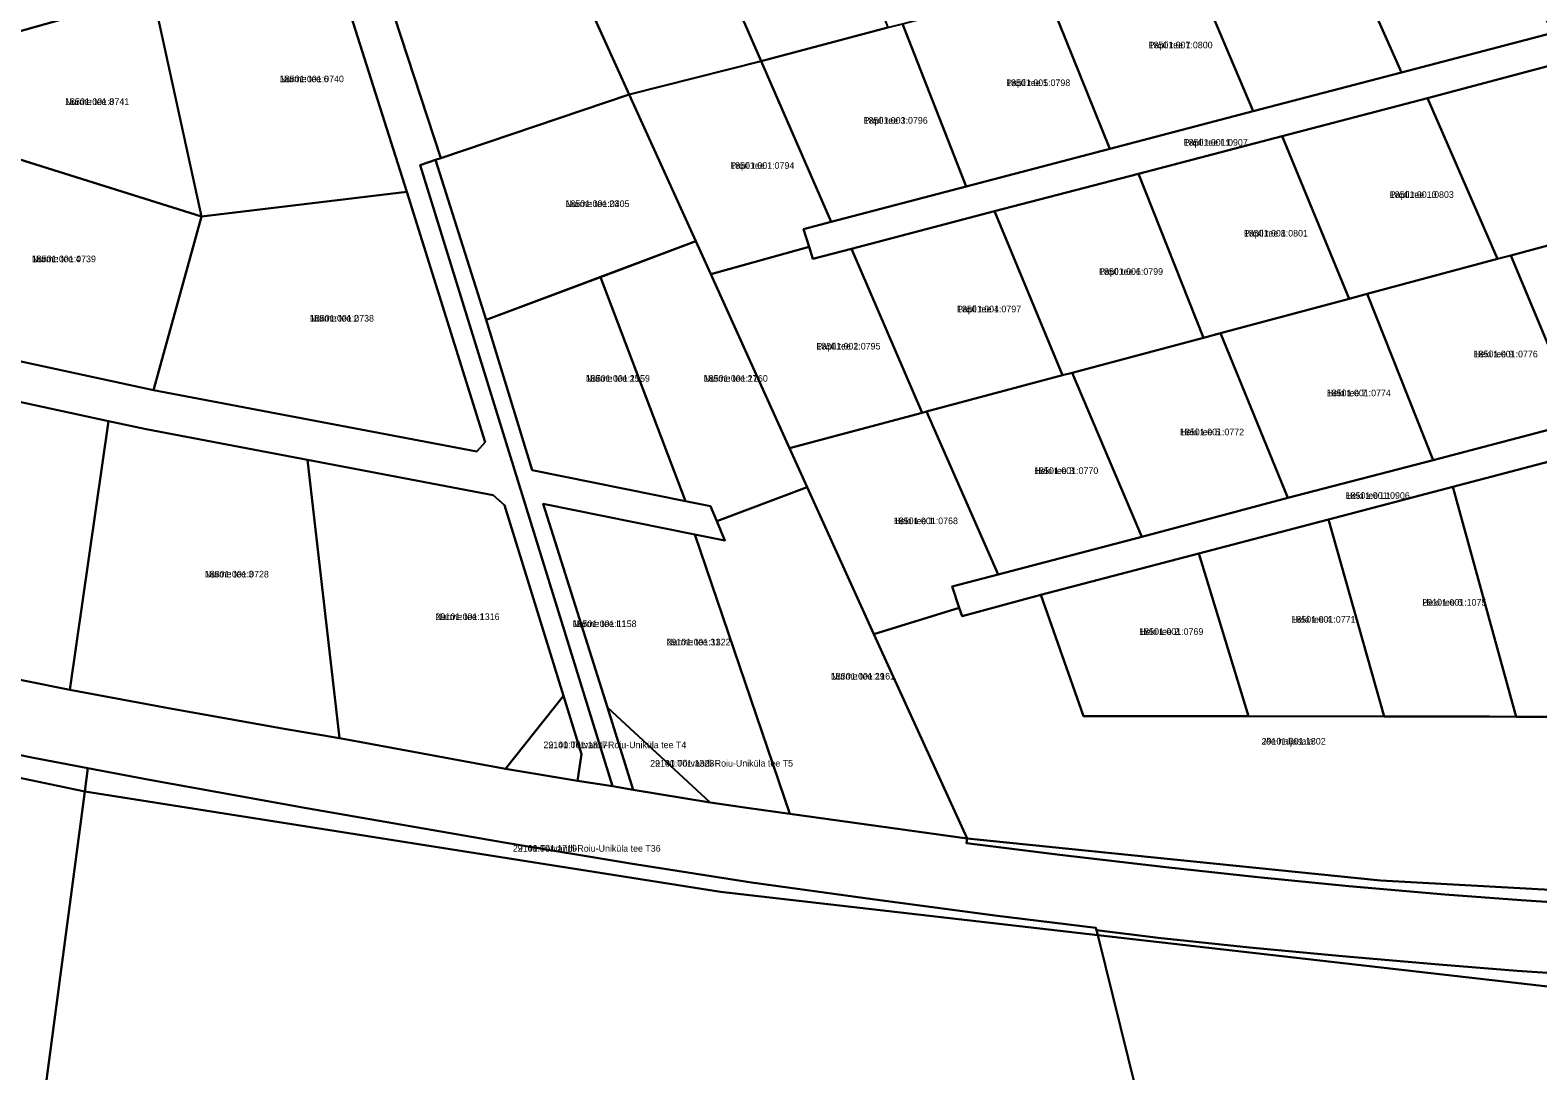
# Model space of a CAD drawing. Extents: x 660838 to 697091, y 6455678 to 6479886.
# Drawn here: x 663753.8 to 664095.1, y 6468179.9 to 6468415.5 of the extents above; entities that cross this region are included whole.
import ezdxf

# ---------------------------------------------------------------- set-up
doc = ezdxf.new("R2010")
doc.units = 0
for name, color, linetype in [('L_AADRESS', 7, 'Continuous'), ('PIIR', 7, 'Continuous'), ('TUNNUS', 7, 'Continuous')]:
    doc.layers.add(name, color=color, linetype=linetype)

msp = doc.modelspace()

# ---------------------------------------------------------------- linework, layer by layer
at = {"layer": 'PIIR'}
for points in [[(663828.73, 6468441.62), (663865.64, 6468453.42), (663871.74, 6468439.96), (663889.41, 6468400.95), (663846.76, 6468386.49)], [(663903.11, 6468445.49), (663933.58, 6468453.47), (663947.98, 6468416.06), (663919.26, 6468408.5)], [(664047.87, 6468442.82), (664071.93, 6468449.23), (664074.89, 6468442.69), (664082.82, 6468445.33), (664098.51, 6468414.91), (664064.26, 6468405.93)], [(663885.65, 6468244.29), (663877.74, 6468245.51), (663878.61, 6468251.58), (663874.54, 6468264.74), (663861.17, 6468307.93), (663858.61, 6468310.23), (663816.6, 6468318.2), (663780.04, 6468325.13), (663771.57, 6468326.94), (663725.97, 6468336.81), (663698.3, 6468342.78), (663700.87, 6468347.01), (663721.55, 6468388.74), (663737.12, 6468420.02), (663744.03, 6468422.46), (663780.76, 6468432.84), (663823.76, 6468445.04), (663828.73, 6468441.62), (663846.76, 6468386.49), (663845.6, 6468386.09), (663842.06, 6468384.89)], [(663871.75, 6468439.96), (663893.39, 6468446.27), (663894.39, 6468443.22), (663903.11, 6468445.49), (663919.26, 6468408.5), (663889.41, 6468400.95)], [(664015.04, 6468434.01), (664042.8, 6468441.46), (664047.87, 6468442.82), (664064.26, 6468405.93), (664030.62, 6468397.11)], [(663854.89, 6468320.1), (663856.77, 6468322.23), (663839.06, 6468378.91), (663821.86, 6468433.12), (663819.34, 6468434.52), (663781.58, 6468423.81), (663747.74, 6468414.2), (663742.48, 6468410.94), (663733.1, 6468391.92), (663713.01, 6468351.64), (663714.75, 6468348.46), (663781.7, 6468333.97)], [(663781.58, 6468423.81), (663819.34, 6468434.52), (663821.86, 6468433.12), (663839.06, 6468378.91), (663792.61, 6468373.3)], [(663983.33, 6468425.52), (664010.69, 6468432.82), (664015.04, 6468434.01), (664030.62, 6468397.11), (663998.2, 6468388.6)], [(663733.1, 6468391.92), (663742.48, 6468410.94), (663747.74, 6468414.2), (663781.58, 6468423.81), (663792.61, 6468373.3)], [(663951.27, 6468416.94), (663978.87, 6468424.33), (663983.33, 6468425.52), (663998.2, 6468388.6), (663965.71, 6468380.05)], [(663919.26, 6468408.5), (663947.98, 6468416.06), (663951.27, 6468416.94), (663965.71, 6468380.05), (663935.15, 6468372.06)], [(664098.51, 6468414.91), (664101.86, 6468408.55), (664070.12, 6468400.11), (664037.18, 6468391.48), (664004.69, 6468382.98), (663972.11, 6468374.47), (663939.71, 6468366), (663931.01, 6468363.73), (663930.12, 6468366.43), (663928.84, 6468370.43), (663935.15, 6468372.06), (663965.71, 6468380.05), (663998.2, 6468388.6), (664030.62, 6468397.11), (664064.26, 6468405.93)], [(663889.41, 6468400.95), (663919.26, 6468408.5), (663935.15, 6468372.06), (663928.84, 6468370.43), (663930.12, 6468366.43), (663907.86, 6468360.21), (663904.5, 6468367.7)], [(664070.12, 6468400.11), (664101.86, 6468408.55), (664119.99, 6468372.84), (664088.98, 6468364.5), (664085.96, 6468363.69)], [(663845.6, 6468386.09), (663846.76, 6468386.49), (663889.41, 6468400.95), (663904.5, 6468367.7), (663857.02, 6468349.93)], [(664037.18, 6468391.48), (664070.12, 6468400.11), (664085.96, 6468363.69), (664056.43, 6468355.76), (664052.4, 6468354.68)], [(663733.1, 6468391.92), (663792.61, 6468373.3), (663781.7, 6468333.97), (663714.75, 6468348.46), (663713.01, 6468351.64)], [(664004.69, 6468382.98), (664037.18, 6468391.48), (664052.4, 6468354.68), (664023.22, 6468346.87), (664019.39, 6468345.85)], [(663885.65, 6468244.29), (663842.06, 6468384.89), (663845.6, 6468386.09), (663857.02, 6468349.93), (663867.45, 6468315.88), (663902.18, 6468308.87), (663907.84, 6468307.73), (663909.27, 6468304.28), (663911.09, 6468299.93), (663904.24, 6468301.31), (663869.9, 6468308.24), (663884.46, 6468262.13), (663890.31, 6468243.48)], [(663972.11, 6468374.47), (664004.69, 6468382.98), (664019.39, 6468345.85), (663989.7, 6468337.93), (663987.53, 6468337.35)], [(663792.61, 6468373.3), (663839.06, 6468378.91), (663856.77, 6468322.23), (663854.89, 6468320.1), (663781.7, 6468333.97)], [(663939.71, 6468366), (663972.11, 6468374.47), (663987.53, 6468337.35), (663956.72, 6468329.11), (663955.71, 6468328.84)], [(664088.98, 6468364.5), (664119.99, 6468372.84), (664138.93, 6468335.94), (664104.7, 6468326.9)], [(663882.88, 6468359.55), (663904.5, 6468367.7), (663907.86, 6468360.21), (663925.72, 6468320.81), (663929.69, 6468312.03), (663909.27, 6468304.28), (663907.84, 6468307.73), (663902.18, 6468308.87)], [(663907.86, 6468360.21), (663930.12, 6468366.43), (663931.01, 6468363.73), (663939.71, 6468366), (663955.71, 6468328.84), (663925.72, 6468320.81)], [(664056.43, 6468355.76), (664085.96, 6468363.69), (664088.98, 6468364.5), (664104.7, 6468326.9), (664071.43, 6468318.15)], [(663857.02, 6468349.93), (663882.88, 6468359.55), (663902.18, 6468308.87), (663867.45, 6468315.88)], [(664023.22, 6468346.87), (664052.4, 6468354.68), (664056.43, 6468355.76), (664071.43, 6468318.15), (664038.5, 6468309.59)], [(663989.7, 6468337.93), (664019.39, 6468345.85), (664023.22, 6468346.87), (664038.5, 6468309.59), (664005.47, 6468300.79)], [(663956.72, 6468329.11), (663987.53, 6468337.35), (663989.7, 6468337.93), (664005.47, 6468300.79), (663972.93, 6468292.22)], [(663725.97, 6468336.81), (663771.57, 6468326.94), (663762.81, 6468266.1), (663731.63, 6468272.38), (663706.42, 6468277.94)], [(664138.93, 6468335.94), (664142.09, 6468329.5), (664103.67, 6468319.4), (664075.84, 6468312.07), (664047.71, 6468304.7), (664018.32, 6468296.96), (663982.59, 6468287.6), (663964.77, 6468282.8), (663964.11, 6468284.71), (663962.55, 6468289.49), (663972.93, 6468292.22), (664005.47, 6468300.79), (664038.5, 6468309.59), (664071.43, 6468318.15), (664104.7, 6468326.9)], [(663925.72, 6468320.81), (663955.71, 6468328.84), (663956.72, 6468329.11), (663972.93, 6468292.22), (663962.55, 6468289.49), (663964.11, 6468284.71), (663944.79, 6468278.74)], [(663771.57, 6468326.94), (663780.04, 6468325.13), (663816.6, 6468318.2), (663823.87, 6468255.19), (663811.79, 6468257.22), (663785.11, 6468262), (663762.81, 6468266.1)], [(663816.6, 6468318.2), (663858.61, 6468310.23), (663861.17, 6468307.93), (663874.54, 6468264.74), (663861.38, 6468248.23), (663823.87, 6468255.19)], [(664075.84, 6468312.07), (664103.67, 6468319.4), (664112.78, 6468291.23), (664111.41, 6468290.88), (664119.66, 6468259.88), (664105.73, 6468259.99), (664090.17, 6468260.05)], [(663909.27, 6468304.28), (663929.69, 6468312.03), (663944.79, 6468278.74), (663965.92, 6468232.47), (663925.77, 6468238.06), (663904.24, 6468301.31), (663911.09, 6468299.93)], [(664047.71, 6468304.7), (664075.84, 6468312.07), (664090.17, 6468260.05), (664084.21, 6468260.09), (664060.31, 6468260.11)], [(663916.01, 6468239.42), (663907.71, 6468240.63), (663884.46, 6468262.13), (663869.9, 6468308.24), (663904.24, 6468301.31), (663925.77, 6468238.06)], [(664018.32, 6468296.96), (664047.71, 6468304.7), (664060.31, 6468260.11), (664029.61, 6468260.17)], [(663982.59, 6468287.6), (664018.32, 6468296.96), (664029.61, 6468260.17), (663992.24, 6468260.2)], [(664117.34, 6468237.15), (664115.71, 6468219.88), (664059.46, 6468222.99), (663965.92, 6468232.47), (663944.79, 6468278.74), (663964.11, 6468284.71), (663964.77, 6468282.8), (663982.59, 6468287.6), (663992.24, 6468260.2), (664029.61, 6468260.17), (664060.31, 6468260.11), (664084.21, 6468260.09), (664090.17, 6468260.05), (664105.73, 6468259.99)], [(663861.38, 6468248.23), (663874.54, 6468264.74), (663878.61, 6468251.58), (663877.74, 6468245.51)], [(663890.31, 6468243.48), (663884.46, 6468262.13), (663907.71, 6468240.63)], [(663910.1, 6468220.42), (663766.16, 6468243.11), (663766.86, 6468248.39), (663780.85, 6468245.76), (663816.37, 6468239.37), (663861.1, 6468231.54), (663889.69, 6468226.78), (663917.07, 6468222.48), (663944.51, 6468218.73), (663972.18, 6468215.04), (663995.06, 6468212.27), (663995.18, 6468211.75), (663995.49, 6468210.56)], [(663965.79, 6468231.38), (663965.92, 6468232.47), (664059.46, 6468222.99), (664115.71, 6468219.88), (664117.34, 6468237.15), (664156.34, 6468234.74), (664171.5, 6468242.59), (664182.99, 6468248.64), (664186.43, 6468241.89), (664201.65, 6468212.63), (664200.48, 6468211.55), (664165.54, 6468213.74), (664122.2, 6468216.46), (664091.28, 6468218.5), (664074.07, 6468219.81), (664052.27, 6468221.67), (664031.71, 6468223.7), (664010.87, 6468226), (663986.88, 6468228.81)], [(663734.7, 6468006.73), (663766.16, 6468243.11), (663910.1, 6468220.42), (663995.49, 6468210.56), (664057.12, 6467961.27), (664125.46, 6467683.34), (663559.65, 6467851.27), (663625.35, 6468044.77), (663626.65, 6468048.6), (663734.39, 6468004.41)], [(664148.88, 6468193.07), (663995.49, 6468210.56), (663995.18, 6468211.75), (664009.18, 6468210.01), (664029.84, 6468207.79), (664050.89, 6468205.83), (664072.71, 6468203.97), (664090.44, 6468202.53), (664121.17, 6468200.49), (664154.73, 6468198.28), (664156.38, 6468189.18)], [(664057.12, 6467961.27), (663995.49, 6468210.56), (664148.88, 6468193.07), (664156.38, 6468189.18), (664156.84, 6468186.18), (664188.82, 6468093.34), (664212.9, 6468021.9), (664222.24, 6467993.73), (664224.85, 6467985.32)]]:
    msp.add_lwpolyline(points, close=True, dxfattribs=at)
for points in [[(663573.38, 6468283.55), (663766.16, 6468243.11), (663734.7, 6468006.73)], [(663727.84, 6468256.2), (663754.55, 6468250.71), (663766.86, 6468248.39), (663766.16, 6468243.11), (663573.38, 6468283.55)], [(663731.63, 6468272.38), (663762.81, 6468266.1), (663785.11, 6468262), (663811.79, 6468257.22), (663823.87, 6468255.19), (663861.38, 6468248.23), (663877.74, 6468245.51), (663885.65, 6468244.29), (663890.31, 6468243.48), (663907.71, 6468240.63), (663916.01, 6468239.42), (663925.77, 6468238.06), (663965.92, 6468232.47), (663965.79, 6468231.38), (663986.88, 6468228.81), (664010.87, 6468226), (664031.71, 6468223.7), (664052.27, 6468221.67), (664074.07, 6468219.81), (664091.28, 6468218.5), (664122.2, 6468216.46)], [(664121.17, 6468200.49), (664090.44, 6468202.53), (664072.71, 6468203.97), (664050.89, 6468205.83), (664029.84, 6468207.79), (664009.18, 6468210.01), (663995.18, 6468211.75), (663995.06, 6468212.27), (663972.18, 6468215.04), (663944.51, 6468218.73), (663917.07, 6468222.48), (663889.69, 6468226.78), (663861.1, 6468231.54), (663816.37, 6468239.37), (663780.85, 6468245.76), (663766.86, 6468248.39), (663754.55, 6468250.71), (663727.84, 6468256.2)]]:
    msp.add_lwpolyline(points, dxfattribs=at)

# ---------------------------------------------------------------- texts
at = {"layer": 'L_AADRESS'}
for s, p in [('Papli tee 7', (664006.97, 6468411.37)), ('Nurme tee 6', (663810.32, 6468403.7)), ('Papli tee 5', (663974.74, 6468402.82)), ('Nurme tee 8', (663761.73, 6468398.55)), ('Papli tee 3', (663942.48, 6468394.3)), ('Papli tee L1', (664014.93, 6468389.32)), ('Papli tee 1', (663912.28, 6468384.09)), ('Papli tee 10', (664061.57, 6468377.51)), ('Nurme tee 23', (663874.98, 6468375.44)), ('Papli tee 8', (664028.54, 6468368.76)), ('Nurme tee 4', (663754.19, 6468362.95)), ('Papli tee 6', (663995.75, 6468360.09)), ('Papli tee 4', (663963.62, 6468351.6)), ('Nurme tee 2', (663817.13, 6468349.51)), ('Papli tee 2', (663931.79, 6468343.18)), ('Heki tee 9', (664080.57, 6468341.4)), ('Nurme tee 25', (663879.6, 6468335.88)), ('Nurme tee 27', (663906.29, 6468335.88)), ('Heki tee 7', (664047.32, 6468332.6)), ('Heki tee 5', (664014.1, 6468323.76)), ('Heki tee 3', (663981.09, 6468315)), ('Heki tee L1', (664051.6, 6468309.37)), ('Heki tee 1', (663949.32, 6468303.64)), ('Nurme tee 3', (663793.34, 6468291.57)), ('Heki tee 6', (664068.94, 6468285.18)), ('Nurme tee 1', (663845.57, 6468281.93)), ('Nurme tee L1', (663876.58, 6468280.33)), ('Heki tee 2', (664004.87, 6468278.57)), ('Heki tee 4', (664039.32, 6468281.32)), ('Nurme tee 31', (663897.84, 6468276.18)), ('Nurme tee 29', (663935.08, 6468268.46)), ('22140 Tõrvandi-Roiu-Uniküla tee T4', (663870, 6468252.92)), ('Jõe haljasala', (664032.56, 6468253.74)), ('22140 Tõrvandi-Roiu-Uniküla tee T5', (663894.16, 6468248.75)), ('22140 Tõrvandi-Roiu-Uniküla tee T36', (663863.08, 6468229.48))]:
    msp.add_text(s, height=1.5, dxfattribs=at).set_placement(p)
at = {"layer": 'TUNNUS'}
for s, p in [('18501:001:0800', (664006.97, 6468411.37)), ('18501:001:0740', (663810.32, 6468403.7)), ('18501:001:0798', (663974.74, 6468402.82)), ('18501:001:0741', (663761.73, 6468398.55)), ('18501:001:0796', (663942.48, 6468394.3)), ('18501:001:0907', (664014.93, 6468389.32)), ('18501:001:0794', (663912.28, 6468384.09)), ('18501:001:0803', (664061.57, 6468377.51)), ('18501:001:0405', (663874.98, 6468375.44)), ('18501:001:0801', (664028.54, 6468368.76)), ('18501:001:0739', (663754.19, 6468362.95)), ('18501:001:0799', (663995.75, 6468360.09)), ('18501:001:0797', (663963.62, 6468351.6)), ('18501:001:0738', (663817.13, 6468349.51)), ('18501:001:0795', (663931.79, 6468343.18)), ('18501:001:0776', (664080.57, 6468341.4)), ('18501:001:1159', (663879.6, 6468335.88)), ('18501:001:1160', (663906.29, 6468335.88)), ('18501:001:0774', (664047.32, 6468332.6)), ('18501:001:0772', (664014.1, 6468323.76)), ('18501:001:0770', (663981.09, 6468315)), ('18501:001:0906', (664051.6, 6468309.37)), ('18501:001:0768', (663949.32, 6468303.64)), ('18501:001:0728', (663793.34, 6468291.57)), ('29101:001:1075', (664068.94, 6468285.18)), ('29101:001:1316', (663845.57, 6468281.93)), ('18501:001:1158', (663876.58, 6468280.33)), ('18501:001:0769', (664004.87, 6468278.57)), ('18501:001:0771', (664039.32, 6468281.32)), ('29101:001:1322', (663897.84, 6468276.18)), ('18501:001:1161', (663935.08, 6468268.46)), ('29101:001:1317', (663870, 6468252.92)), ('29101:001:1302', (664032.56, 6468253.74)), ('29101:001:1323', (663894.16, 6468248.75)), ('29101:001:1719', (663863.08, 6468229.48))]:
    msp.add_text(s, height=1.5, dxfattribs=at).set_placement(p)

doc.saveas('drawing.dxf')
